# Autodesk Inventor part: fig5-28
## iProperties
Created: 2004-05
Part Number: fig5-28
Document SubType Name: Modeling
Designer: CADCIM Technologies
Manufacturer: Standard
Standards Organization: Custom
Author: CADCIM Technologies
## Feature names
1. Extrusion1
2. Extrusion2
3. Hole1
4. Fillet5
